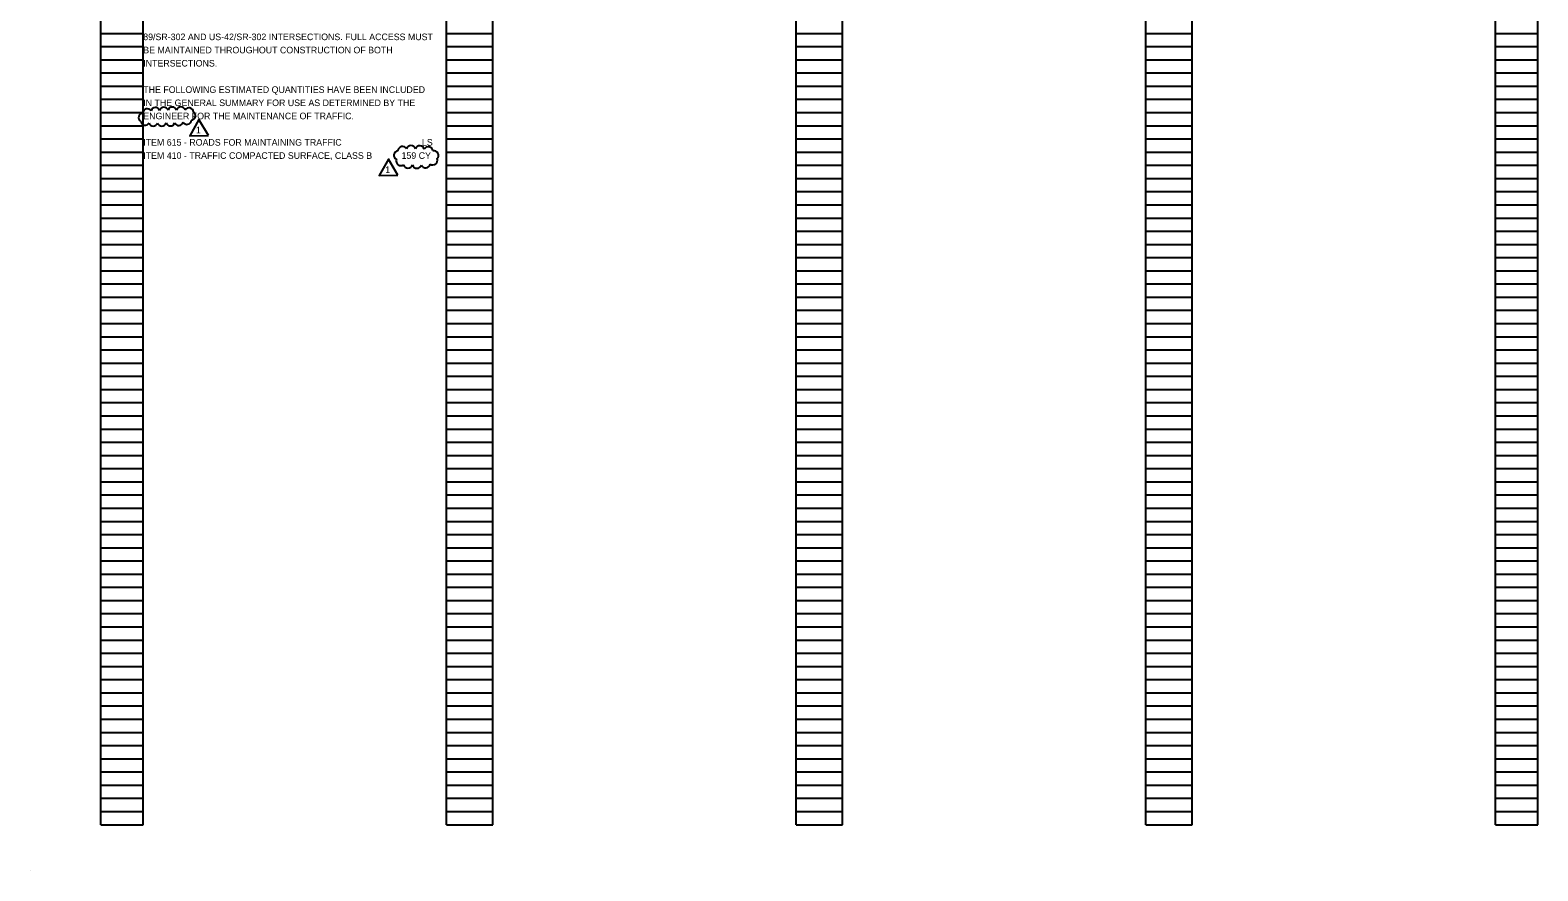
# Model space of a CAD drawing. Extents: x -9 to 32, y -122 to 20.
# Drawn here: x -0.28 to 31.72, y -121.63 to -103.79 of the extents above; entities that cross this region are included whole.
import ezdxf

# ---------------------------------------------------------------- set-up
doc = ezdxf.new("R2010")
doc.units = 0
for name, color, linetype in [('SC_Scratch1', 7, 'Continuous'), ('SC_Scratch2', 7, 'Continuous'), ('SH_Text', 7, 'Continuous')]:
    doc.layers.add(name, color=color, linetype=linetype)

msp = doc.modelspace()

# ---------------------------------------------------------------- linework, layer by layer
at = {"layer": 'SC_Scratch1'}
for p, q in [((1.216, -120.654), (1.216, -100.494)), ((2.116, -120.654), (2.116, -100.494)), ((8.556, -120.654), (8.556, -100.494)), ((9.536, -120.654), (9.536, -100.494)), ((15.976, -120.654), (15.976, -100.494)), ((16.956, -120.654), (16.956, -100.494)), ((23.396, -120.654), (23.396, -100.494)), ((24.376, -120.654), (24.376, -100.494)), ((30.816, -120.654), (30.816, -100.494)), ((31.716, -120.654), (31.716, -100.494)), ((1.216, -103.854), (2.116, -103.854)), ((8.556, -103.854), (9.536, -103.854)), ((15.976, -103.854), (16.956, -103.854)), ((23.396, -103.854), (24.376, -103.854)), ((30.816, -103.854), (31.716, -103.854)), ((1.216, -104.134), (2.116, -104.134)), ((8.556, -104.134), (9.536, -104.134)), ((15.976, -104.134), (16.956, -104.134)), ((23.396, -104.134), (24.376, -104.134)), ((30.816, -104.134), (31.716, -104.134)), ((1.216, -104.414), (2.116, -104.414)), ((8.556, -104.414), (9.536, -104.414)), ((15.976, -104.414), (16.956, -104.414)), ((23.396, -104.414), (24.376, -104.414)), ((30.816, -104.414), (31.716, -104.414)), ((1.216, -104.694), (2.116, -104.694)), ((8.556, -104.694), (9.536, -104.694)), ((15.976, -104.694), (16.956, -104.694)), ((23.396, -104.694), (24.376, -104.694)), ((30.816, -104.694), (31.716, -104.694)), ((1.216, -104.974), (2.116, -104.974)), ((1.216, -105.254), (2.116, -105.254)), ((8.556, -104.974), (9.536, -104.974)), ((8.556, -105.254), (9.536, -105.254)), ((15.976, -104.974), (16.956, -104.974)), ((15.976, -105.254), (16.956, -105.254)), ((23.396, -104.974), (24.376, -104.974)), ((23.396, -105.254), (24.376, -105.254)), ((30.816, -104.974), (31.716, -104.974)), ((30.816, -105.254), (31.716, -105.254)), ((1.216, -105.534), (2.116, -105.534)), ((8.556, -105.534), (9.536, -105.534)), ((15.976, -105.534), (16.956, -105.534)), ((23.396, -105.534), (24.376, -105.534)), ((30.816, -105.534), (31.716, -105.534)), ((1.216, -105.814), (2.116, -105.814)), ((8.556, -105.814), (9.536, -105.814)), ((15.976, -105.814), (16.956, -105.814)), ((23.396, -105.814), (24.376, -105.814)), ((30.816, -105.814), (31.716, -105.814)), ((1.216, -106.094), (2.116, -106.094)), ((8.556, -106.094), (9.536, -106.094)), ((15.976, -106.094), (16.956, -106.094)), ((23.396, -106.094), (24.376, -106.094)), ((30.816, -106.094), (31.716, -106.094)), ((1.216, -106.374), (2.116, -106.374)), ((8.556, -106.374), (9.536, -106.374)), ((15.976, -106.374), (16.956, -106.374)), ((23.396, -106.374), (24.376, -106.374)), ((30.816, -106.374), (31.716, -106.374)), ((1.216, -106.654), (2.116, -106.654)), ((8.556, -106.654), (9.536, -106.654)), ((15.976, -106.654), (16.956, -106.654)), ((23.396, -106.654), (24.376, -106.654)), ((30.816, -106.654), (31.716, -106.654)), ((1.216, -106.934), (2.116, -106.934)), ((8.556, -106.934), (9.536, -106.934)), ((15.976, -106.934), (16.956, -106.934)), ((23.396, -106.934), (24.376, -106.934)), ((30.816, -106.934), (31.716, -106.934)), ((1.216, -107.214), (2.116, -107.214)), ((1.216, -107.494), (2.116, -107.494)), ((8.556, -107.214), (9.536, -107.214)), ((8.556, -107.494), (9.536, -107.494)), ((15.976, -107.214), (16.956, -107.214)), ((15.976, -107.494), (16.956, -107.494)), ((23.396, -107.214), (24.376, -107.214)), ((23.396, -107.494), (24.376, -107.494)), ((30.816, -107.214), (31.716, -107.214)), ((30.816, -107.494), (31.716, -107.494)), ((1.216, -107.774), (2.116, -107.774)), ((8.556, -107.774), (9.536, -107.774)), ((15.976, -107.774), (16.956, -107.774)), ((23.396, -107.774), (24.376, -107.774)), ((30.816, -107.774), (31.716, -107.774)), ((1.216, -108.054), (2.116, -108.054)), ((8.556, -108.054), (9.536, -108.054)), ((15.976, -108.054), (16.956, -108.054)), ((23.396, -108.054), (24.376, -108.054)), ((30.816, -108.054), (31.716, -108.054)), ((1.216, -108.334), (2.116, -108.334)), ((8.556, -108.334), (9.536, -108.334)), ((15.976, -108.334), (16.956, -108.334)), ((23.396, -108.334), (24.376, -108.334)), ((30.816, -108.334), (31.716, -108.334)), ((1.216, -108.614), (2.116, -108.614)), ((8.556, -108.614), (9.536, -108.614)), ((15.976, -108.614), (16.956, -108.614)), ((23.396, -108.614), (24.376, -108.614)), ((30.816, -108.614), (31.716, -108.614)), ((1.216, -108.894), (2.116, -108.894)), ((8.556, -108.894), (9.536, -108.894)), ((15.976, -108.894), (16.956, -108.894)), ((23.396, -108.894), (24.376, -108.894)), ((30.816, -108.894), (31.716, -108.894)), ((1.216, -109.174), (2.116, -109.174)), ((8.556, -109.174), (9.536, -109.174)), ((15.976, -109.174), (16.956, -109.174)), ((23.396, -109.174), (24.376, -109.174)), ((30.816, -109.174), (31.716, -109.174)), ((1.216, -109.454), (2.116, -109.454)), ((1.216, -109.734), (2.116, -109.734)), ((8.556, -109.454), (9.536, -109.454)), ((8.556, -109.734), (9.536, -109.734)), ((15.976, -109.454), (16.956, -109.454)), ((15.976, -109.734), (16.956, -109.734)), ((23.396, -109.454), (24.376, -109.454)), ((23.396, -109.734), (24.376, -109.734)), ((30.816, -109.454), (31.716, -109.454)), ((30.816, -109.734), (31.716, -109.734)), ((1.216, -110.014), (2.116, -110.014)), ((8.556, -110.014), (9.536, -110.014)), ((15.976, -110.014), (16.956, -110.014)), ((23.396, -110.014), (24.376, -110.014)), ((30.816, -110.014), (31.716, -110.014)), ((1.216, -110.294), (2.116, -110.294)), ((8.556, -110.294), (9.536, -110.294)), ((15.976, -110.294), (16.956, -110.294)), ((23.396, -110.294), (24.376, -110.294)), ((30.816, -110.294), (31.716, -110.294)), ((1.216, -110.574), (2.116, -110.574)), ((8.556, -110.574), (9.536, -110.574)), ((15.976, -110.574), (16.956, -110.574)), ((23.396, -110.574), (24.376, -110.574)), ((30.816, -110.574), (31.716, -110.574)), ((1.216, -110.854), (2.116, -110.854)), ((8.556, -110.854), (9.536, -110.854)), ((15.976, -110.854), (16.956, -110.854)), ((23.396, -110.854), (24.376, -110.854)), ((30.816, -110.854), (31.716, -110.854)), ((1.216, -111.134), (2.116, -111.134)), ((8.556, -111.134), (9.536, -111.134)), ((15.976, -111.134), (16.956, -111.134)), ((23.396, -111.134), (24.376, -111.134)), ((30.816, -111.134), (31.716, -111.134)), ((1.216, -111.414), (2.116, -111.414)), ((8.556, -111.414), (9.536, -111.414)), ((15.976, -111.414), (16.956, -111.414)), ((23.396, -111.414), (24.376, -111.414)), ((30.816, -111.414), (31.716, -111.414)), ((1.216, -111.694), (2.116, -111.694)), ((1.216, -111.974), (2.116, -111.974)), ((8.556, -111.694), (9.536, -111.694)), ((8.556, -111.974), (9.536, -111.974)), ((15.976, -111.694), (16.956, -111.694)), ((15.976, -111.974), (16.956, -111.974)), ((23.396, -111.694), (24.376, -111.694)), ((23.396, -111.974), (24.376, -111.974)), ((30.816, -111.694), (31.716, -111.694)), ((30.816, -111.974), (31.716, -111.974)), ((1.216, -112.254), (2.116, -112.254)), ((8.556, -112.254), (9.536, -112.254)), ((15.976, -112.254), (16.956, -112.254)), ((23.396, -112.254), (24.376, -112.254)), ((30.816, -112.254), (31.716, -112.254)), ((1.216, -112.534), (2.116, -112.534)), ((8.556, -112.534), (9.536, -112.534)), ((15.976, -112.534), (16.956, -112.534)), ((23.396, -112.534), (24.376, -112.534)), ((30.816, -112.534), (31.716, -112.534)), ((1.216, -112.814), (2.116, -112.814)), ((8.556, -112.814), (9.536, -112.814)), ((15.976, -112.814), (16.956, -112.814)), ((23.396, -112.814), (24.376, -112.814)), ((30.816, -112.814), (31.716, -112.814)), ((1.216, -113.094), (2.116, -113.094)), ((8.556, -113.094), (9.536, -113.094)), ((15.976, -113.094), (16.956, -113.094)), ((23.396, -113.094), (24.376, -113.094)), ((30.816, -113.094), (31.716, -113.094)), ((1.216, -113.374), (2.116, -113.374)), ((8.556, -113.374), (9.536, -113.374)), ((15.976, -113.374), (16.956, -113.374)), ((23.396, -113.374), (24.376, -113.374)), ((30.816, -113.374), (31.716, -113.374)), ((1.216, -113.654), (2.116, -113.654)), ((8.556, -113.654), (9.536, -113.654)), ((15.976, -113.654), (16.956, -113.654)), ((23.396, -113.654), (24.376, -113.654)), ((30.816, -113.654), (31.716, -113.654)), ((1.216, -113.934), (2.116, -113.934)), ((1.216, -114.214), (2.116, -114.214)), ((8.556, -113.934), (9.536, -113.934)), ((8.556, -114.214), (9.536, -114.214)), ((15.976, -113.934), (16.956, -113.934)), ((15.976, -114.214), (16.956, -114.214)), ((23.396, -113.934), (24.376, -113.934)), ((23.396, -114.214), (24.376, -114.214)), ((30.816, -113.934), (31.716, -113.934)), ((30.816, -114.214), (31.716, -114.214)), ((1.216, -114.494), (2.116, -114.494)), ((8.556, -114.494), (9.536, -114.494)), ((15.976, -114.494), (16.956, -114.494)), ((23.396, -114.494), (24.376, -114.494)), ((30.816, -114.494), (31.716, -114.494)), ((1.216, -114.774), (2.116, -114.774)), ((8.556, -114.774), (9.536, -114.774)), ((15.976, -114.774), (16.956, -114.774)), ((23.396, -114.774), (24.376, -114.774)), ((30.816, -114.774), (31.716, -114.774)), ((1.216, -115.054), (2.116, -115.054)), ((8.556, -115.054), (9.536, -115.054)), ((15.976, -115.054), (16.956, -115.054)), ((23.396, -115.054), (24.376, -115.054)), ((30.816, -115.054), (31.716, -115.054)), ((1.216, -115.334), (2.116, -115.334)), ((8.556, -115.334), (9.536, -115.334)), ((15.976, -115.334), (16.956, -115.334)), ((23.396, -115.334), (24.376, -115.334)), ((30.816, -115.334), (31.716, -115.334)), ((1.216, -115.614), (2.116, -115.614)), ((8.556, -115.614), (9.536, -115.614)), ((15.976, -115.614), (16.956, -115.614)), ((23.396, -115.614), (24.376, -115.614)), ((30.816, -115.614), (31.716, -115.614)), ((1.216, -115.894), (2.116, -115.894)), ((8.556, -115.894), (9.536, -115.894)), ((15.976, -115.894), (16.956, -115.894)), ((23.396, -115.894), (24.376, -115.894)), ((30.816, -115.894), (31.716, -115.894)), ((1.216, -116.174), (2.116, -116.174)), ((1.216, -116.454), (2.116, -116.454)), ((8.556, -116.174), (9.536, -116.174)), ((8.556, -116.454), (9.536, -116.454)), ((15.976, -116.174), (16.956, -116.174)), ((15.976, -116.454), (16.956, -116.454)), ((23.396, -116.174), (24.376, -116.174)), ((23.396, -116.454), (24.376, -116.454)), ((30.816, -116.174), (31.716, -116.174)), ((30.816, -116.454), (31.716, -116.454)), ((1.216, -116.734), (2.116, -116.734)), ((8.556, -116.734), (9.536, -116.734)), ((15.976, -116.734), (16.956, -116.734)), ((23.396, -116.734), (24.376, -116.734)), ((30.816, -116.734), (31.716, -116.734)), ((1.216, -117.014), (2.116, -117.014)), ((8.556, -117.014), (9.536, -117.014)), ((15.976, -117.014), (16.956, -117.014)), ((23.396, -117.014), (24.376, -117.014)), ((30.816, -117.014), (31.716, -117.014)), ((1.216, -117.294), (2.116, -117.294)), ((8.556, -117.294), (9.536, -117.294)), ((15.976, -117.294), (16.956, -117.294)), ((23.396, -117.294), (24.376, -117.294)), ((30.816, -117.294), (31.716, -117.294)), ((1.216, -117.574), (2.116, -117.574)), ((8.556, -117.574), (9.536, -117.574)), ((15.976, -117.574), (16.956, -117.574)), ((23.396, -117.574), (24.376, -117.574)), ((30.816, -117.574), (31.716, -117.574)), ((1.216, -117.854), (2.116, -117.854)), ((8.556, -117.854), (9.536, -117.854)), ((15.976, -117.854), (16.956, -117.854)), ((23.396, -117.854), (24.376, -117.854)), ((30.816, -117.854), (31.716, -117.854)), ((1.216, -118.134), (2.116, -118.134)), ((8.556, -118.134), (9.536, -118.134)), ((15.976, -118.134), (16.956, -118.134)), ((23.396, -118.134), (24.376, -118.134)), ((30.816, -118.134), (31.716, -118.134)), ((1.216, -118.414), (2.116, -118.414)), ((1.216, -118.694), (2.116, -118.694)), ((8.556, -118.414), (9.536, -118.414)), ((8.556, -118.694), (9.536, -118.694)), ((15.976, -118.414), (16.956, -118.414)), ((15.976, -118.694), (16.956, -118.694)), ((23.396, -118.414), (24.376, -118.414)), ((23.396, -118.694), (24.376, -118.694)), ((30.816, -118.414), (31.716, -118.414)), ((30.816, -118.694), (31.716, -118.694)), ((1.216, -118.974), (2.116, -118.974)), ((8.556, -118.974), (9.536, -118.974)), ((15.976, -118.974), (16.956, -118.974)), ((23.396, -118.974), (24.376, -118.974)), ((30.816, -118.974), (31.716, -118.974)), ((1.216, -119.254), (2.116, -119.254)), ((8.556, -119.254), (9.536, -119.254)), ((15.976, -119.254), (16.956, -119.254)), ((23.396, -119.254), (24.376, -119.254)), ((30.816, -119.254), (31.716, -119.254)), ((1.216, -119.534), (2.116, -119.534)), ((8.556, -119.534), (9.536, -119.534)), ((15.976, -119.534), (16.956, -119.534)), ((23.396, -119.534), (24.376, -119.534)), ((30.816, -119.534), (31.716, -119.534)), ((1.216, -119.814), (2.116, -119.814)), ((8.556, -119.814), (9.536, -119.814)), ((15.976, -119.814), (16.956, -119.814)), ((23.396, -119.814), (24.376, -119.814)), ((30.816, -119.814), (31.716, -119.814)), ((1.216, -120.094), (2.116, -120.094)), ((8.556, -120.094), (9.536, -120.094)), ((15.976, -120.094), (16.956, -120.094)), ((23.396, -120.094), (24.376, -120.094)), ((30.816, -120.094), (31.716, -120.094)), ((1.216, -120.374), (2.116, -120.374)), ((8.556, -120.374), (9.536, -120.374)), ((15.976, -120.374), (16.956, -120.374)), ((23.396, -120.374), (24.376, -120.374)), ((30.816, -120.374), (31.716, -120.374)), ((1.216, -120.654), (2.116, -120.654)), ((8.556, -120.654), (9.536, -120.654)), ((15.976, -120.654), (16.956, -120.654)), ((23.396, -120.654), (24.376, -120.654)), ((30.816, -120.654), (31.716, -120.654)), ((-0.284, -121.634), (-0.284, -121.634))]:
    msp.add_line(p, q, dxfattribs=at)
at = {"layer": 'SC_Scratch2'}
for points in [[(3.503, -106.023), (3.299, -105.68), (3.105, -106.028)], [(7.523, -106.867), (7.318, -106.524), (7.124, -106.872)]]:
    msp.add_lwpolyline(points, close=True, dxfattribs=at)
for centre, radius, start, end in [((2.112, -105.641), 0.0947, 92.6451, 237.6451), ((2.203, -105.549), 0.0947, 33.1215, 178.1215), ((2.374, -105.522), 0.0947, 19.8647, 164.8647), ((2.554, -105.517), 0.0947, 18.7766, 163.7766), ((2.734, -105.513), 0.0947, 18.4716, 163.4716), ((2.915, -105.51), 0.0947, 18.2549, 163.2549), ((3.086, -105.53), 0.0948, 3.8568, 148.8568), ((3.131, -105.604), 0.0947, 273.9149, 58.9149), ((2.156, -105.709), 0.0947, 186.9382, 331.9382), ((2.33, -105.727), 0.0947, 196.4166, 341.4166), ((2.51, -105.728), 0.0947, 198.2312, 343.2312), ((2.69, -105.725), 0.0947, 198.8348, 343.8348), ((2.87, -105.717), 0.0947, 201.278, 346.278), ((3.043, -105.691), 0.0947, 210.3408, 355.3408), ((7.798, -106.333), 0.0988, 17.8289, 162.8289), ((7.984, -106.339), 0.0988, 13.7247, 158.7247), ((7.534, -106.443), 0.0988, 98.3234, 243.3234), ((7.584, -106.563), 0.0988, 161.4781, 306.4781), ((7.619, -106.354), 0.0988, 30.2106, 175.2106), ((8.168, -106.361), 0.0988, 7.3984, 152.3984), ((8.263, -106.547), 0.0988, 234.6967, 19.6967), ((8.285, -106.445), 0.0987, 316.1893, 101.1893), ((7.737, -106.615), 0.0988, 195.7098, 340.7098), ((7.925, -106.619), 0.0988, 196.9155, 341.9155), ((8.109, -106.609), 0.0988, 204.3825, 349.3825)]:
    msp.add_arc(centre, radius, start, end, dxfattribs=at)

# ---------------------------------------------------------------- texts
for p in [(3.233, -105.975), (7.253, -106.818)]:
    msp.add_text('1', height=0.14, dxfattribs=at).set_placement(p)
at = {"layer": 'SH_Text'}
for s, p in [('89/SR-302 AND US-42/SR-302 INTERSECTIONS. FULL ACCESS MUST ', (2.116, -103.998)), ('BE MAINTAINED THROUGHOUT CONSTRUCTION OF BOTH ', (2.116, -104.278)), ('INTERSECTIONS.', (2.116, -104.558)), ('THE FOLLOWING ESTIMATED QUANTITIES HAVE BEEN INCLUDED ', (2.116, -105.118)), ('IN THE GENERAL SUMMARY FOR USE AS DETERMINED BY THE ', (2.116, -105.398)), ('ENGINEER FOR THE MAINTENANCE OF TRAFFIC.', (2.116, -105.678)), ('ITEM 615 - ROADS FOR MAINTAINING TRAFFIC', (2.116, -106.238)), ('LS', (8.031, -106.238)), ('ITEM 410 - TRAFFIC COMPACTED SURFACE, CLASS B', (2.116, -106.518)), ('159 CY', (7.598, -106.518))]:
    msp.add_text(s, height=0.14, dxfattribs=at).set_placement(p)

doc.saveas('drawing.dxf')
